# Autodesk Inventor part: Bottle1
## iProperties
Company: Autodesk
Shininess: 64.0
Length Units: 11272
Angle Units: 11279
Time Units: 11290
Mass Units: 11286
Length Display Precision: 3
Angle Display Precision: 2
Compacted: True
Part Number: Bottle1
Document SubType Name: Modeling
Created: 2004-03
Designer: The PD Team
Manufacturer: Standard
Standards Organization: Custom
Project: Inventor Samples
Density: 0.0
Volumn: 0.0
Area: 0.0
PropertySet Name: Model Information
Control State: 0
Master: False
Checked Out: False
Author: The PD Team
Revision Number: A
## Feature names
1. Split4
2. Split5
3. Fillet1
4. Fillet2
